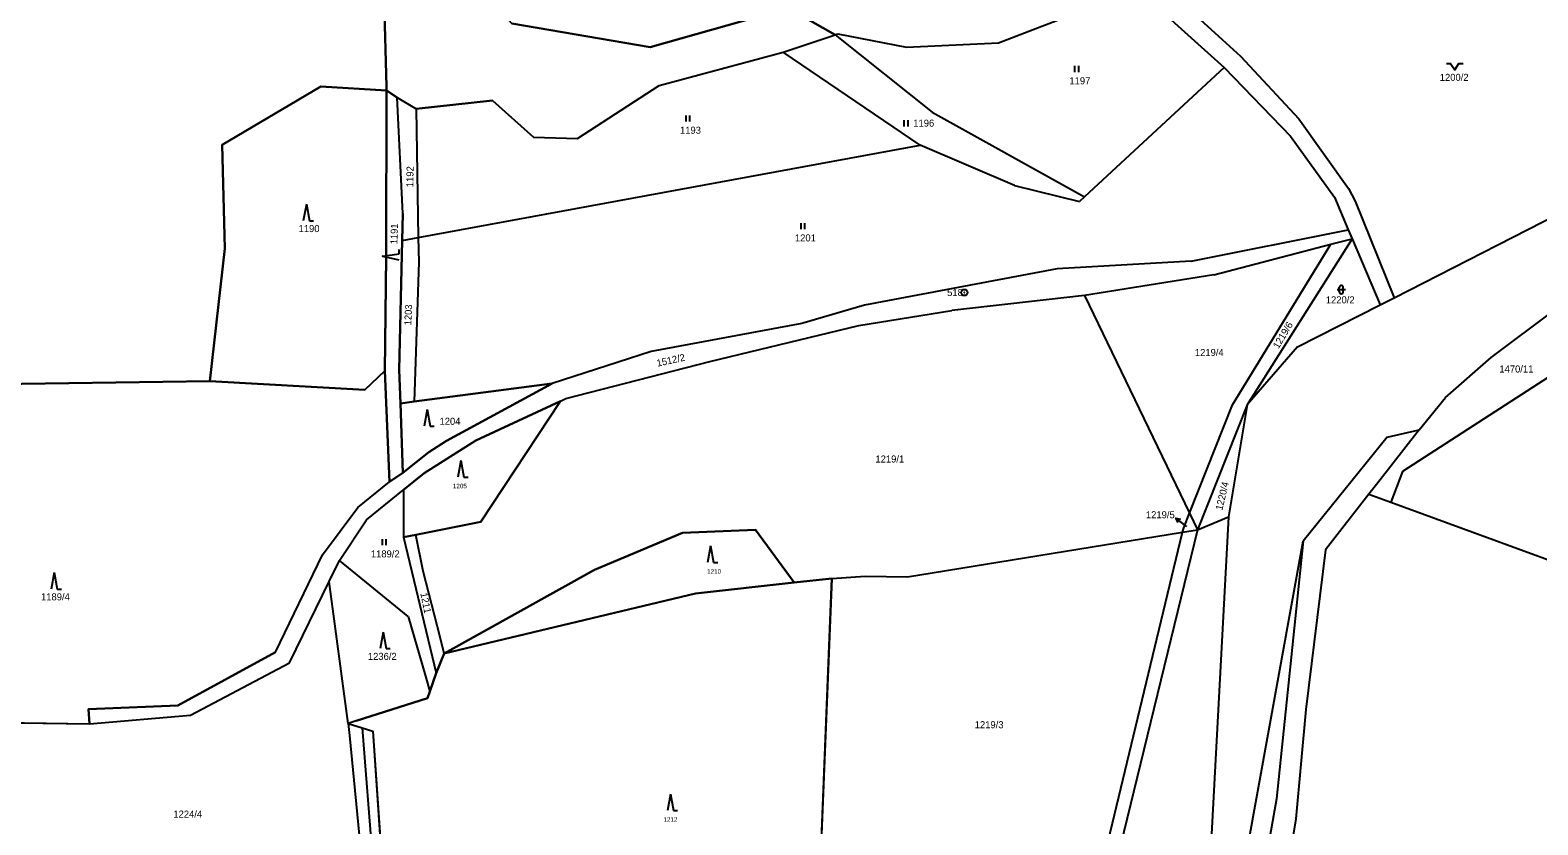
# Model space of a CAD drawing. Extents: x -760642 to -757221, y -1092371 to -1088855.
# Drawn here: x -759236.4 to -758872.5, y -1091071.1 to -1090879.2 of the extents above; entities that cross this region are included whole.
import ezdxf

# ---------------------------------------------------------------- set-up
doc = ezdxf.new("R2010")
doc.units = 0
for name, color, linetype in [('Vrstva 1', 7, 'Continuous'), ('Vrstva 16', 7, 'Continuous'), ('Vrstva 17', 7, 'Continuous'), ('Vrstva 18', 7, 'Continuous'), ('Vrstva 24', 7, 'Continuous'), ('Vrstva 25', 7, 'Continuous'), ('Vrstva 30', 7, 'Continuous')]:
    doc.layers.add(name, color=color, linetype=linetype)

msp = doc.modelspace()

# ---------------------------------------------------------------- linework, layer by layer
at = {"layer": 'Vrstva 1'}
for p, q in [((-758967.79, -1090864.06), (-758944.21, -1090885.52)), ((-758971.82, -1090866.92), (-758948.18, -1090888.24)), ((-759150.4, -1090892.85), (-759150.92, -1090872.11)), ((-759086.75, -1090883.38), (-759053.39, -1090873.96)), ((-759053.39, -1090873.96), (-759042.11, -1090880.34)), ((-759002.68, -1090882.33), (-758981.05, -1090874.05)), ((-759120.09, -1090877.65), (-759086.75, -1090883.38)), ((-759042.11, -1090880.34), (-759041.4, -1090880.14)), ((-759041.4, -1090880.14), (-759024.86, -1090883.32)), ((-759054.59, -1090884.54), (-759042.11, -1090880.34)), ((-759042.11, -1090880.34), (-759018.63, -1090899.05)), ((-759024.86, -1090883.32), (-759002.68, -1090882.33)), ((-759084.53, -1090892.6), (-759054.59, -1090884.54)), ((-759021.58, -1090906.97), (-759054.59, -1090884.54)), ((-758944.21, -1090885.52), (-758930.17, -1090900.68)), ((-758948.18, -1090888.24), (-758981.88, -1090919.49)), ((-758948.18, -1090888.24), (-758932.18, -1090904.87)), ((-759166.24, -1090892.82), (-759190.05, -1090906.9)), ((-759150.4, -1090893.77), (-759166.24, -1090892.82)), ((-759150.49, -1090933.85), (-759150.4, -1090893.77)), ((-759150.4, -1090893.77), (-759150.4, -1090892.85)), ((-759150.4, -1090893.77), (-759147.8, -1090895.52)), ((-759104.3, -1090905.41), (-759084.53, -1090892.6)), ((-759147.8, -1090895.52), (-759143.25, -1090898.24)), ((-759146.41, -1090923.49), (-759147.8, -1090895.52)), ((-759124.76, -1090896.25), (-759143.25, -1090898.24)), ((-759143.25, -1090898.24), (-759142.7, -1090929.3)), ((-759124.76, -1090896.25), (-759114.86, -1090905.07)), ((-759018.63, -1090899.05), (-758981.88, -1090919.49)), ((-758930.17, -1090900.68), (-758918.15, -1090917.44)), ((-759114.86, -1090905.07), (-759104.3, -1090905.41)), ((-758932.18, -1090904.87), (-758921.57, -1090919.57)), ((-759190.05, -1090906.9), (-759189.37, -1090931.98)), ((-759142.7, -1090929.3), (-759021.58, -1090906.97)), ((-758998.82, -1090916.73), (-759021.58, -1090906.97)), ((-758998.82, -1090916.73), (-758983.1, -1090920.63)), ((-758981.88, -1090919.49), (-758983.1, -1090920.63)), ((-758921.57, -1090919.57), (-758918.22, -1090927.43)), ((-758918.15, -1090917.44), (-758916.56, -1090920.54)), ((-758907.14, -1090943.82), (-758854.07, -1090916.72)), ((-759146.41, -1090923.49), (-759146.57, -1090930.01)), ((-758916.56, -1090920.54), (-758907.14, -1090943.82)), ((-758956.15, -1090935.03), (-758918.22, -1090927.43)), ((-758918.22, -1090927.43), (-758917.3, -1090929.6)), ((-759146.57, -1090930.01), (-759147.31, -1090961.25)), ((-759146.57, -1090930.01), (-759142.7, -1090929.3)), ((-759142.7, -1090929.3), (-759142.59, -1090935.28)), ((-758950.64, -1090938.33), (-758922.4, -1090930.94)), ((-758946.14, -1090969.7), (-758922.4, -1090930.94)), ((-758917.3, -1090929.6), (-758942.6, -1090969.66)), ((-758922.4, -1090930.94), (-758917.3, -1090929.6)), ((-758917.3, -1090929.6), (-758910.5, -1090945.53)), ((-759189.37, -1090931.98), (-759193.04, -1090963.98)), ((-759150.8, -1090961.51), (-759150.49, -1090933.85)), ((-759142.59, -1090935.28), (-759143.69, -1090968.9)), ((-758988.46, -1090936.84), (-759035.02, -1090945.61)), ((-758956.15, -1090935.03), (-758988.46, -1090936.84)), ((-758950.64, -1090938.33), (-758981.87, -1090943.28)), ((-759035.02, -1090945.61), (-759050.16, -1090950.08)), ((-758981.87, -1090943.28), (-759013.93, -1090946.89)), ((-758981.87, -1090943.28), (-758956.55, -1090995.88)), ((-758930.44, -1090955.71), (-758910.5, -1090945.53)), ((-758910.5, -1090945.53), (-758907.14, -1090943.82)), ((-759036.36, -1090950.52), (-759013.93, -1090946.89)), ((-758883.73, -1090958.28), (-758868.35, -1090946.78)), ((-759050.16, -1090950.08), (-759086.46, -1090956.8)), ((-759072.35, -1090959.26), (-759036.36, -1090950.52)), ((-758930.44, -1090955.71), (-758942.6, -1090969.66)), ((-759086.46, -1090956.8), (-759110.41, -1090964.54)), ((-759107.06, -1090968.16), (-759072.35, -1090959.26)), ((-758894.75, -1090967.94), (-758883.73, -1090958.28)), ((-759155.59, -1090966.06), (-759150.8, -1090961.51)), ((-759149.68, -1090988.26), (-759150.8, -1090961.51)), ((-759147.31, -1090961.25), (-759147.03, -1090969.33)), ((-758869.93, -1090963.05), (-758905.14, -1090985.82)), ((-759249.8, -1090964.81), (-759193.04, -1090963.98)), ((-759193.04, -1090963.98), (-759155.59, -1090966.06)), ((-759143.69, -1090968.9), (-759110.41, -1090964.54)), ((-759110.41, -1090964.54), (-759135.88, -1090978.36)), ((-759147.03, -1090969.33), (-759143.69, -1090968.9)), ((-759147.03, -1090969.33), (-759146.46, -1090986.11)), ((-759128.83, -1090978.31), (-759108.41, -1090968.79)), ((-759127.57, -1090997.97), (-759108.41, -1090968.79)), ((-759108.41, -1090968.79), (-759107.06, -1090968.16)), ((-758956.55, -1090995.88), (-758946.14, -1090969.7)), ((-758942.6, -1090969.66), (-758954.65, -1090999.83)), ((-758942.6, -1090969.66), (-758947.12, -1090996.71)), ((-758901.1, -1090975.73), (-758894.75, -1090967.94)), ((-759141.3, -1090986.19), (-759128.83, -1090978.31)), ((-759135.88, -1090978.36), (-759140.17, -1090981.09)), ((-758908.87, -1090977.53), (-758929.14, -1091002.61)), ((-758901.1, -1090975.73), (-758911.12, -1090988.55)), ((-758908.87, -1090977.53), (-758901.1, -1090975.73)), ((-759140.17, -1090981.09), (-759146.46, -1090986.11)), ((-759157.26, -1090994.48), (-759149.68, -1090988.26)), ((-759146.46, -1090986.11), (-759149.68, -1090988.26)), ((-759146.27, -1090990.23), (-759141.3, -1090986.19)), ((-758911.12, -1090988.55), (-758913.25, -1090991.28)), ((-758905.14, -1090985.82), (-758907.93, -1090993.22)), ((-759155.18, -1090997.44), (-759146.27, -1090990.23)), ((-759146.27, -1090990.23), (-759146.28, -1091001.66)), ((-758913.25, -1090991.28), (-758923.72, -1091004.69)), ((-758913.25, -1090991.28), (-758907.93, -1090993.22)), ((-759165.82, -1091005.92), (-759157.26, -1090994.48)), ((-758957.95, -1090999.39), (-758956.55, -1090995.88)), ((-758956.55, -1090995.88), (-758954.65, -1090999.83)), ((-758954.65, -1090999.83), (-758947.12, -1090996.71)), ((-758947.12, -1090996.71), (-758952.13, -1091090.22)), ((-758907.93, -1090993.22), (-758844.16, -1091016.49)), ((-759161.75, -1091007.27), (-759155.18, -1090997.44)), ((-759127.57, -1090997.97), (-759143.28, -1091001.06)), ((-759078.89, -1091000.57), (-759061.27, -1090999.88)), ((-759061.27, -1090999.88), (-759051.97, -1091012.58)), ((-758954.65, -1090999.83), (-758977.88, -1091095.27)), ((-758958.2, -1091000.41), (-758957.95, -1090999.39)), ((-758958.2, -1091000.41), (-758954.65, -1090999.83)), ((-759143.28, -1091001.06), (-759146.28, -1091001.66)), ((-759146.28, -1091001.66), (-759138.35, -1091034.48)), ((-759141.54, -1091009.82), (-759143.28, -1091001.06)), ((-759100.17, -1091009.52), (-759078.89, -1091000.57)), ((-759024.59, -1091011.23), (-758958.2, -1091000.41)), ((-758980.66, -1091093.56), (-758958.2, -1091000.41)), ((-758942.74, -1091077.56), (-758929.14, -1091002.61)), ((-758929.14, -1091002.61), (-758935.58, -1091064.77)), ((-759177.15, -1091029.41), (-759165.82, -1091005.92)), ((-759164.21, -1091012.3), (-759161.75, -1091007.27)), ((-759145.17, -1091020.76), (-759161.75, -1091007.27)), ((-758923.72, -1091004.69), (-758928.5, -1091043.27)), ((-759137.43, -1091025.81), (-759141.54, -1091009.82)), ((-759136.43, -1091029.71), (-759100.17, -1091009.52)), ((-759042.91, -1091011.58), (-759034.84, -1091011.06)), ((-759034.84, -1091011.06), (-759024.59, -1091011.23)), ((-759173.8, -1091031.93), (-759164.21, -1091012.3)), ((-759159.59, -1091046.59), (-759164.21, -1091012.3)), ((-759075.82, -1091015.2), (-759051.97, -1091012.58)), ((-759051.97, -1091012.58), (-759042.91, -1091011.58)), ((-759042.91, -1091011.58), (-759046.21, -1091094.96)), ((-759136.43, -1091029.71), (-759075.82, -1091015.2)), ((-759145.17, -1091020.76), (-759140.99, -1091035.17)), ((-759136.43, -1091029.71), (-759137.43, -1091025.81)), ((-759177.15, -1091029.41), (-759200.78, -1091042.3)), ((-759197.67, -1091044.62), (-759173.8, -1091031.93)), ((-759138.35, -1091034.48), (-759136.43, -1091029.71)), ((-759140.99, -1091035.17), (-759139.91, -1091038.89)), ((-759139.91, -1091038.89), (-759138.35, -1091034.48)), ((-759140.47, -1091040.49), (-759139.91, -1091038.89)), ((-759200.78, -1091042.3), (-759222.3, -1091043.15)), ((-759222.3, -1091043.15), (-759222.07, -1091046.67)), ((-759157.69, -1091045.98), (-759140.47, -1091040.49)), ((-758928.5, -1091043.27), (-758930.86, -1091069.64)), ((-759253.49, -1091046.24), (-759222.07, -1091046.67)), ((-759222.07, -1091046.67), (-759197.67, -1091044.62)), ((-759157.69, -1091045.98), (-759159.59, -1091046.59)), ((-759159.59, -1091046.59), (-759159.27, -1091049.54)), ((-759159.59, -1091046.59), (-759156.25, -1091047.63)), ((-759156.25, -1091047.63), (-759153.67, -1091048.44)), ((-759156.25, -1091047.63), (-759153.54, -1091082.53)), ((-759159.27, -1091049.54), (-759155.79, -1091086.27)), ((-759153.67, -1091048.44), (-759151.04, -1091086.98)), ((-758935.58, -1091064.77), (-758943.2, -1091107.81)), ((-758930.86, -1091069.64), (-758935.74, -1091098.59))]:
    msp.add_line(p, q, dxfattribs=at)
at = {"layer": 'Vrstva 16'}
for p, q in [((-758957.43, -1090998.9), (-758959.807, -1090997.07)), ((-758957.2, -1090999.08), (-758957.43, -1090998.9))]:
    msp.add_line(p, q, dxfattribs=at)
msp.add_lwpolyline([(-758959.32, -1090998.076), (-758959.807, -1090997.07), (-758958.709, -1090997.284)], dxfattribs=at)
at = {"layer": 'Vrstva 24'}
for radius in [0.75, 0.0327]:
    msp.add_circle((-759010.89, -1090942.57), radius, dxfattribs=at)
at = {"layer": 'Vrstva 25'}
for p, q in [((-758984.277, -1090887.885), (-758984.277, -1090889.385)), ((-758983.255, -1090889.385), (-758983.255, -1090887.885)), ((-759078.147, -1090899.815), (-759078.147, -1090901.315)), ((-759077.125, -1090901.315), (-759077.125, -1090899.815)), ((-759025.477, -1090900.975), (-759025.477, -1090902.475)), ((-759024.455, -1090902.475), (-759024.455, -1090900.975)), ((-759169.722, -1090921.279), (-759170.455, -1090925.279)), ((-759169.722, -1090921.279), (-759168.989, -1090925.279)), ((-759168.989, -1090925.279), (-759167.989, -1090925.279)), ((-759050.397, -1090925.815), (-759050.397, -1090927.315)), ((-759049.375, -1090927.315), (-759049.375, -1090925.815)), ((-759151.358, -1090933.817), (-759147.337, -1090933.209)), ((-759151.358, -1090933.817), (-759147.383, -1090934.674)), ((-759147.337, -1090933.209), (-759147.306, -1090932.21)), ((-758920.92, -1090941.87), (-758918.92, -1090941.87)), ((-758920.42, -1090942.37), (-758920.42, -1090941.37)), ((-758919.42, -1090942.37), (-758919.42, -1090941.37)), ((-759140.582, -1090970.829), (-759141.315, -1090974.829)), ((-759140.582, -1090970.829), (-759139.849, -1090974.829)), ((-759139.849, -1090974.829), (-759138.849, -1090974.829)), ((-759132.412, -1090983.129), (-759133.145, -1090987.129)), ((-759132.412, -1090983.129), (-759131.679, -1090987.129)), ((-759131.679, -1090987.129), (-759130.679, -1090987.129)), ((-759151.457, -1091002.085), (-759151.457, -1091003.585)), ((-759150.435, -1091003.585), (-759150.435, -1091002.085)), ((-759072.152, -1091003.749), (-759072.885, -1091007.749)), ((-759072.152, -1091003.749), (-759071.419, -1091007.749)), ((-759230.582, -1091010.179), (-759231.315, -1091014.179)), ((-759230.582, -1091010.179), (-759229.849, -1091014.179)), ((-759071.419, -1091007.749), (-759070.419, -1091007.749)), ((-759229.849, -1091014.179), (-759228.849, -1091014.179)), ((-759151.202, -1091024.549), (-759151.935, -1091028.549)), ((-759151.202, -1091024.549), (-759150.469, -1091028.549)), ((-759150.469, -1091028.549), (-759149.469, -1091028.549)), ((-759081.842, -1091063.639), (-759082.575, -1091067.639)), ((-759081.842, -1091063.639), (-759081.109, -1091067.639)), ((-759081.109, -1091067.639), (-759080.109, -1091067.639))]:
    msp.add_line(p, q, dxfattribs=at)
msp.add_lwpolyline([(-758894.53, -1090887.29), (-758893.53, -1090887.29), (-758892.53, -1090888.79), (-758891.53, -1090887.29), (-758890.53, -1090887.29)], dxfattribs=at)
for centre, start, end in [((-758919.92, -1090941.37), 0, 180), ((-758919.92, -1090942.37), 180, 0)]:
    msp.add_arc(centre, 0.5, start, end, dxfattribs=at)
at = {"layer": 'Vrstva 30'}
for points in [[(-759156.05, -1090818.26), (-759155.34, -1090850.18), (-759150.92, -1090872.11), (-759150.4, -1090892.85), (-759150.4, -1090893.77), (-759147.8, -1090895.52), (-759143.25, -1090898.24), (-759124.76, -1090896.25), (-759114.86, -1090905.07), (-759104.3, -1090905.41), (-759084.53, -1090892.6), (-759054.59, -1090884.54), (-759042.11, -1090880.34), (-759053.39, -1090873.96), (-759086.75, -1090883.38), (-759120.09, -1090877.65), (-759132.34, -1090863.69), (-759128.18, -1090841.12), (-759156.7, -1090806.56), (-759156.05, -1090818.26)], [(-759285.97, -1090965.54), (-759288.49, -1090965.11), (-759308.73, -1090944.83), (-759316.09, -1090948.44), (-759343.4, -1090904.08), (-759332.48, -1090903.52), (-759333.53, -1090886.84), (-759324.95, -1090889.1), (-759284.64, -1090886.09), (-759275.4, -1090892.75), (-759249.06, -1090957.11), (-759249.8, -1090964.81), (-759193.04, -1090963.98), (-759189.37, -1090931.98), (-759190.05, -1090906.9), (-759166.24, -1090892.82), (-759150.4, -1090893.77), (-759150.4, -1090892.85), (-759150.92, -1090872.11)], [(-759150.492, -1090934.004), (-759151.358, -1090933.817), (-759150.49, -1090933.686), (-759150.4, -1090893.77), (-759166.24, -1090892.82), (-759190.05, -1090906.9), (-759189.37, -1090931.98), (-759193.04, -1090963.98), (-759155.59, -1090966.06), (-759150.8, -1090961.51), (-759150.492, -1090934.004)], [(-759150.492, -1090934.004), (-759150.8, -1090961.51), (-759149.68, -1090988.26), (-759146.46, -1090986.11), (-759147.03, -1090969.33), (-759147.31, -1090961.25), (-759146.57, -1090930.01), (-759146.41, -1090923.49), (-759147.8, -1090895.52), (-759150.4, -1090893.77), (-759150.49, -1090933.686), (-759150.49, -1090933.85), (-759150.492, -1090934.004)], [(-758818.58, -1090951.71), (-758829.44, -1090921.53), (-758829.64, -1090920.27), (-758850.38, -1090934.3), (-758869.93, -1090963.05), (-758905.14, -1090985.82), (-758907.93, -1090993.22), (-758844.16, -1091016.49), (-758796.93, -1091033.69), (-758802.1, -1091018.55), (-758803.12, -1090997.11), (-758818.58, -1090951.71)], [(-759253.49, -1091046.24), (-759222.07, -1091046.67), (-759222.3, -1091043.15), (-759200.78, -1091042.3), (-759177.15, -1091029.41), (-759165.82, -1091005.92), (-759157.26, -1090994.48), (-759149.68, -1090988.26), (-759150.8, -1090961.51), (-759155.59, -1090966.06), (-759193.04, -1090963.98), (-759249.8, -1090964.81)], [(-759143.69, -1090968.9), (-759147.03, -1090969.33), (-759146.46, -1090986.11), (-759140.17, -1090981.09), (-759135.88, -1090978.36), (-759110.41, -1090964.54), (-759143.69, -1090968.9)], [(-759146.28, -1091001.66), (-759143.28, -1091001.06), (-759127.57, -1090997.97), (-759108.41, -1090968.79), (-759128.83, -1090978.31), (-759141.3, -1090986.19), (-759146.27, -1090990.23), (-759146.28, -1091001.66)], [(-759051.97, -1091012.58), (-759061.27, -1090999.88), (-759078.89, -1091000.57), (-759100.17, -1091009.52), (-759136.43, -1091029.71), (-759075.82, -1091015.2), (-759051.97, -1091012.58)], [(-759143.28, -1091001.06), (-759146.28, -1091001.66), (-759138.35, -1091034.48), (-759136.43, -1091029.71), (-759137.43, -1091025.81), (-759141.54, -1091009.82), (-759143.28, -1091001.06)], [(-759014.13, -1091129.723), (-759040.85, -1091112.69), (-759046.21, -1091094.96), (-759042.91, -1091011.58), (-759051.97, -1091012.58), (-759075.82, -1091015.2), (-759136.43, -1091029.71), (-759138.35, -1091034.48), (-759139.91, -1091038.89), (-759140.47, -1091040.49), (-759157.69, -1091045.98), (-759159.59, -1091046.59), (-759156.25, -1091047.63), (-759153.67, -1091048.44), (-759151.365, -1091082.21), (-759151.04, -1091086.98), (-759151.31, -1091119.29), (-759150.16, -1091119.3), (-759086.14, -1091121.04), (-759050.46, -1091119.52), (-759038.69, -1091123.83), (-759038.175, -1091122.335)]]:
    msp.add_lwpolyline(points, dxfattribs=at)

# ---------------------------------------------------------------- texts
at = {"layer": 'Vrstva 16'}
msp.add_text('1219/5', height=1.7, dxfattribs=at).set_placement((-758967.069, -1090997.07))
at = {"layer": 'Vrstva 17'}
msp.add_text('518', height=1.7, dxfattribs=at).set_placement((-759015.051, -1090943.42))
at = {"layer": 'Vrstva 18'}
for s, height, p in [('1197', 1.7, (-758985.54, -1090892.32)), ('1200/2', 1.7, (-758896.14, -1090891.49)), ('1196', 1.7, (-759023.22, -1090902.53)), ('1193', 1.7, (-759079.53, -1090904.25)), ('1190', 1.7, (-759171.6, -1090927.99)), ('1201', 1.7, (-759051.79, -1090930.25)), ('1220/2', 1.7, (-758923.65, -1090945.19)), ('1219/4', 1.7, (-758955.25, -1090957.9)), ('1470/11', 1.7, (-758881.76, -1090961.89)), ('1204', 1.7, (-759137.58, -1090974.51)), ('1219/1', 1.7, (-759032.36, -1090983.62)), ('1205', 1.1, (-759134.366, -1090989.84)), ('1219/5', 0.1, (-758957.346, -1090999.08)), ('1189/2', 1.7, (-759154.15, -1091006.52)), ('1210', 1.1, (-759072.987, -1091010.46)), ('1189/4', 1.7, (-759233.766, -1091016.89)), ('1236/2', 1.7, (-759154.87, -1091031.26)), ('1219/3', 1.7, (-759008.39, -1091047.76)), ('1224/4', 1.7, (-759201.82, -1091069.33)), ('1212', 1.1, (-759083.538, -1091070.35))]:
    msp.add_text(s, height=height, dxfattribs=at).set_placement(p)
for s, rotation, p in [('1192', 88.88976, (-759143.92, -1090917.16)), ('1191', 88.21008, (-759147.754, -1090930.98)), ('1203', 87.11838, (-759144.42, -1090950.54)), ('1219/6', 59.07906, (-758935.07, -1090956.28)), ('1512/2', 12.42387, (-759084.97, -1090960.49)), ('1220/4', 76.73436, (-758948.63, -1090995.26)), ('1211', 281.42262, (-759142.21, -1091015.19))]:
    msp.add_text(s, height=1.7, rotation=rotation, dxfattribs=at).set_placement(p)

doc.saveas('drawing.dxf')
